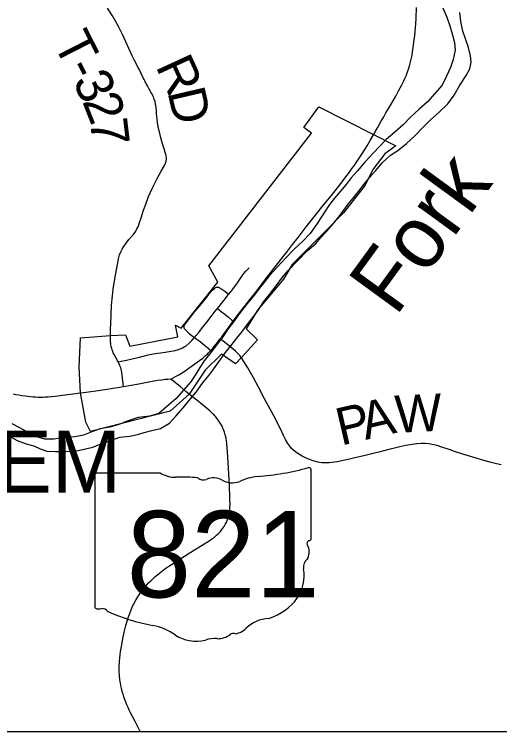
# Model space of a CAD drawing. Extents: x -10.5 to 40.6, y -3.2 to 22.
# Drawn here: x -8.513 to -7.773, y 14.1 to 15.194 of the extents above; entities that cross this region are included whole.
import ezdxf

# ---------------------------------------------------------------- set-up
doc = ezdxf.new("R2010")
doc.units = 0
for name, color, linetype in [('GM_X_City_Street', 7, 'Continuous'), ('GM_X_Corporation_Text', 7, 'Continuous'), ('GM_X_Major_River', 7, 'Continuous'), ('GM_X_Major_River_Text', 7, 'Continuous'), ('GM_X_State_Location', 7, 'Continuous'), ('GM_X_State_Route', 7, 'Continuous'), ('GM_X_State_Shield', 7, 'Continuous'), ('GM_X_Township_Road', 7, 'Continuous'), ('GM_X_Township_Road_Text', 7, 'Continuous'), ('GM_X_Township_Text', 7, 'Continuous'), ('SH_Text', 7, 'Continuous')]:
    doc.layers.add(name, color=color, linetype=linetype)

msp = doc.modelspace()

# ---------------------------------------------------------------- linework, layer by layer
at = {"layer": 'GM_X_City_Street'}
for points in [[(-8.3549, 14.6638), (-8.35, 14.6648), (-8.3422, 14.6664), (-8.3332, 14.6684), (-8.3223, 14.6711), (-8.309, 14.6743), (-8.3011, 14.6759), (-8.2943, 14.6769), (-8.2863, 14.6781), (-8.268, 14.6813), (-8.2626, 14.6828), (-8.2568, 14.685), (-8.254, 14.6864), (-8.2509, 14.6884), (-8.2466, 14.6921), (-8.2422, 14.6964), (-8.2389, 14.7002), (-8.2385, 14.7008), (-8.2359, 14.7041), (-8.2317, 14.7087), (-8.229, 14.7121), (-8.2259, 14.716), (-8.2193, 14.7243), (-8.213, 14.7327), (-8.2066, 14.7411), (-8.2033, 14.7451), (-8.2008, 14.7482), (-8.1935, 14.7574), (-8.1913, 14.7602), (-8.1901, 14.7619), (-8.1889, 14.7636), (-8.1864, 14.7666), (-8.183, 14.7706), (-8.1799, 14.7744), (-8.173, 14.784), (-8.1669, 14.7934), (-8.1633, 14.7984), (-8.1601, 14.8022), (-8.1557, 14.8067), (-8.1549, 14.8076)], [(-8.2546, 14.7169), (-8.2543, 14.7181), (-8.254, 14.7186), (-8.2534, 14.7197), (-8.2523, 14.7212), (-8.2442, 14.732), (-8.2377, 14.7403), (-8.2302, 14.7494), (-8.2177, 14.765), (-8.2163, 14.7667), (-8.2145, 14.7688), (-8.2132, 14.7703), (-8.2118, 14.7718), (-8.2103, 14.7733), (-8.2087, 14.7748), (-8.2079, 14.7755), (-8.2073, 14.776), (-8.2067, 14.7764), (-8.2057, 14.777), (-8.205, 14.7774), (-8.204, 14.7777), (-8.2029, 14.7778), (-8.2017, 14.7775), (-8.2009, 14.7771), (-8.2002, 14.7768), (-8.1994, 14.7763), (-8.1986, 14.7758), (-8.1975, 14.7751), (-8.1967, 14.7746), (-8.192, 14.7714), (-8.1901, 14.7699), (-8.187, 14.7672), (-8.1864, 14.7666)], [(-8.2033, 14.7451), (-8.2014, 14.7436), (-8.1977, 14.7406), (-8.1923, 14.7363), (-8.1866, 14.7317), (-8.1814, 14.7275), (-8.1793, 14.7258)], [(-8.2546, 14.7169), (-8.2546, 14.7158), (-8.2541, 14.7147), (-8.2533, 14.7137), (-8.2527, 14.713), (-8.2521, 14.7124), (-8.2471, 14.7077), (-8.2415, 14.703), (-8.2385, 14.7008), (-8.2363, 14.6991), (-8.2299, 14.6946), (-8.2231, 14.6894), (-8.2179, 14.6851), (-8.2169, 14.6843), (-8.2132, 14.681)]]:
    msp.add_lwpolyline(points, dxfattribs=at)
at = {"layer": 'GM_X_Major_River'}
for points in [[(-7.8595, 15.2033), (-7.8536, 15.1894), (-7.8489, 15.1761), (-7.8453, 15.1637), (-7.8421, 15.1504), (-7.8411, 15.1387), (-7.844, 15.1246), (-7.848, 15.1124), (-7.8539, 15.0991), (-7.8609, 15.0857), (-7.8717, 15.073), (-7.8833, 15.06), (-7.8957, 15.0488), (-7.9092, 15.0368), (-7.92, 15.0253), (-7.9331, 15.0137), (-7.9459, 15.0026), (-7.9563, 14.9922), (-7.9653, 14.9826), (-7.9784, 14.968), (-7.9903, 14.9545), (-7.9997, 14.9442), (-8.0071, 14.9342), (-8.0161, 14.9234), (-8.0276, 14.91), (-8.0343, 14.9004), (-8.0436, 14.8863), (-8.0522, 14.8729), (-8.0622, 14.8595), (-8.0734, 14.8479), (-8.0869, 14.8352), (-8.0992, 14.8225), (-8.1123, 14.8083), (-8.1239, 14.7956), (-8.131, 14.786), (-8.1399, 14.7757), (-8.1466, 14.7661), (-8.1575, 14.753), (-8.1686, 14.7392), (-8.1787, 14.7247), (-8.1873, 14.7136), (-8.1951, 14.7021), (-8.204, 14.6906), (-8.2152, 14.6756), (-8.2234, 14.6653), (-8.2304, 14.6549), (-8.2364, 14.645), (-8.2442, 14.6327), (-8.2554, 14.6201), (-8.267, 14.6074), (-8.2812, 14.5954), (-8.2928, 14.585), (-8.3068, 14.581), (-8.3242, 14.5789), (-8.3393, 14.5738), (-8.3536, 14.5683), (-8.3676, 14.5643), (-8.382, 14.5614), (-8.3948, 14.5571), (-8.4076, 14.552), (-8.4209, 14.5495), (-8.4413, 14.5477), (-8.453, 14.5457), (-8.4667, 14.5459), (-8.4789, 14.5495), (-8.4918, 14.5561), (-8.5056, 14.5639), (-8.5163, 14.5691)], [(-8.5225, 14.5516), (-8.5087, 14.5438), (-8.495, 14.5386), (-8.4832, 14.5358), (-8.4737, 14.5313), (-8.4634, 14.5277), (-8.4509, 14.5271), (-8.4388, 14.5269), (-8.4259, 14.5274), (-8.4157, 14.5287), (-8.4043, 14.5311), (-8.3934, 14.5339), (-8.3798, 14.5391), (-8.3666, 14.5438), (-8.3519, 14.5489), (-8.3367, 14.5506), (-8.3254, 14.5531), (-8.3152, 14.5563), (-8.3035, 14.5591), (-8.2899, 14.5623), (-8.2763, 14.5701), (-8.2666, 14.5812), (-8.2558, 14.5935), (-8.2476, 14.6038), (-8.2356, 14.6173), (-8.226, 14.6311), (-8.2163, 14.643), (-8.2088, 14.6529), (-8.2014, 14.6637), (-8.191, 14.6782), (-8.1809, 14.6905), (-8.1738, 14.7001), (-8.1652, 14.7104), (-8.157, 14.7216), (-8.1481, 14.7334), (-8.1406, 14.743), (-8.1325, 14.7557), (-8.1239, 14.7664), (-8.1123, 14.7817), (-8.1042, 14.7929), (-8.0956, 14.8032), (-8.0668, 14.8328), (-8.0537, 14.8436), (-8.0451, 14.8536), (-8.0365, 14.8632), (-8.0268, 14.8744), (-8.016, 14.8874), (-8.004, 14.9039), (-7.9962, 14.9135), (-7.9884, 14.9234), (-7.9798, 14.9346), (-7.9716, 14.9449), (-7.9619, 14.9553), (-7.9522, 14.9672), (-7.9395, 14.9787), (-7.9282, 14.9857), (-7.9151, 14.9965), (-7.9023, 15.0085), (-7.8892, 15.0219), (-7.8784, 15.0327), (-7.8653, 15.0446), (-7.8522, 15.057), (-7.8425, 15.0704), (-7.834, 15.0853), (-7.8243, 15.1002), (-7.8188, 15.1105), (-7.8166, 15.1208), (-7.8175, 15.1303), (-7.8204, 15.1431), (-7.8259, 15.1575), (-7.829, 15.1681), (-7.8323, 15.1828), (-7.834, 15.1965)]]:
    msp.add_lwpolyline(points, dxfattribs=at)
at = {"layer": 'GM_X_State_Route'}
for points in [[(-7.9653, 15.0099), (-7.9636, 15.0131), (-7.9618, 15.0164), (-7.9594, 15.0207), (-7.9563, 15.026), (-7.9536, 15.0309), (-7.9498, 15.0373), (-7.9464, 15.0433), (-7.9417, 15.0513), (-7.9321, 15.068), (-7.9273, 15.0767), (-7.9229, 15.0849), (-7.9194, 15.0921), (-7.9172, 15.0965), (-7.9157, 15.0999), (-7.9135, 15.1057), (-7.912, 15.1101), (-7.9105, 15.1151), (-7.9094, 15.1192), (-7.9084, 15.1234), (-7.9075, 15.1271), (-7.9067, 15.1312), (-7.9058, 15.1361), (-7.9042, 15.1465), (-7.9033, 15.1551), (-7.9026, 15.1606), (-7.902, 15.1674), (-7.9015, 15.1729), (-7.9011, 15.1791), (-7.9005, 15.1878), (-7.8998, 15.2038)], [(-8.2742, 14.6374), (-8.2672, 14.6412), (-8.261, 14.6447), (-8.2539, 14.6491), (-8.2486, 14.6529), (-8.2305, 14.6659), (-8.2256, 14.6696), (-8.2213, 14.6732), (-8.2187, 14.6755), (-8.2168, 14.6773), (-8.2132, 14.681), (-8.2111, 14.6835), (-8.2087, 14.6864), (-8.2052, 14.6907), (-8.2022, 14.6947), (-8.1997, 14.6982), (-8.1991, 14.6989), (-8.1974, 14.7011), (-8.1931, 14.7072), (-8.1887, 14.7132), (-8.1852, 14.7181), (-8.182, 14.7222), (-8.1793, 14.7258), (-8.1711, 14.7365), (-8.164, 14.7458), (-8.1585, 14.7528), (-8.1532, 14.7594), (-8.1465, 14.7682), (-8.1404, 14.7762), (-8.126, 14.7949), (-8.1028, 14.8247), (-8.0982, 14.8305), (-8.0903, 14.8408), (-8.0887, 14.8427), (-8.0803, 14.8535), (-8.0679, 14.8697), (-8.0558, 14.8847), (-8.0477, 14.8949), (-8.045, 14.8983), (-8.032, 14.9145), (-8.0238, 14.9245), (-8.0147, 14.9363), (-8.0077, 14.9457), (-8.0022, 14.953), (-7.9977, 14.9592), (-7.9941, 14.9642), (-7.9913, 14.9682), (-7.9851, 14.9774), (-7.9821, 14.9821), (-7.9753, 14.9933), (-7.9704, 15.0013), (-7.9653, 15.0099)], [(-8.2742, 14.6374), (-8.279, 14.637), (-8.2832, 14.6366), (-8.288, 14.636), (-8.2945, 14.6352), (-8.3079, 14.6328), (-8.3234, 14.6299), (-8.3466, 14.6256), (-8.3557, 14.624), (-8.3815, 14.6203), (-8.4036, 14.6172), (-8.4119, 14.616)], [(-8.2467, 14.6146), (-8.2509, 14.6181), (-8.2599, 14.6256), (-8.2703, 14.6342), (-8.2742, 14.6374)], [(-8.4737, 14.6096), (-8.4764, 14.6096), (-8.4807, 14.6099), (-8.4845, 14.6101), (-8.4881, 14.6104), (-8.4922, 14.6108), (-8.496, 14.6113), (-8.5015, 14.6121), (-8.506, 14.6128), (-8.5105, 14.6137), (-8.5142, 14.6146)], [(-8.4119, 14.616), (-8.4508, 14.6109), (-8.4564, 14.6104), (-8.4614, 14.61), (-8.4655, 14.6097), (-8.4689, 14.6096), (-8.4729, 14.6096), (-8.4737, 14.6096)], [(-8.1847, 14.4355), (-8.1843, 14.4399), (-8.1842, 14.4431), (-8.1841, 14.446), (-8.1841, 14.4484), (-8.1842, 14.4509), (-8.1842, 14.454), (-8.1843, 14.4571), (-8.1844, 14.4607), (-8.1845, 14.4632), (-8.1848, 14.4686), (-8.1849, 14.4716), (-8.1851, 14.4752), (-8.187, 14.5104), (-8.1879, 14.5267), (-8.1889, 14.5384), (-8.189, 14.5403), (-8.1893, 14.5422), (-8.1895, 14.5437), (-8.1898, 14.5458), (-8.19, 14.547), (-8.1903, 14.5484), (-8.1906, 14.5499), (-8.191, 14.5512), (-8.1914, 14.5527), (-8.1919, 14.5545), (-8.1925, 14.5564), (-8.1934, 14.5592), (-8.1939, 14.5604), (-8.1944, 14.5615), (-8.195, 14.5629), (-8.1956, 14.5641), (-8.1968, 14.5665), (-8.198, 14.5686), (-8.1996, 14.5712), (-8.201, 14.5733), (-8.2028, 14.5757), (-8.2037, 14.577), (-8.2049, 14.5784), (-8.206, 14.5798), (-8.2073, 14.5814), (-8.2085, 14.5828), (-8.2099, 14.5842), (-8.2112, 14.5855), (-8.2126, 14.5867), (-8.2149, 14.5889), (-8.2181, 14.5916), (-8.2261, 14.5981), (-8.235, 14.6052), (-8.2409, 14.6099), (-8.246, 14.614), (-8.2467, 14.6146)], [(-8.321, 14.1), (-8.3289, 14.1155), (-8.3357, 14.1288), (-8.3377, 14.1327), (-8.3395, 14.1367), (-8.3414, 14.1408), (-8.3429, 14.1447), (-8.3445, 14.149), (-8.3459, 14.153), (-8.3472, 14.1569), (-8.3485, 14.1612), (-8.3497, 14.1661), (-8.3506, 14.1704), (-8.3513, 14.1743), (-8.3517, 14.1766), (-8.352, 14.1788), (-8.3523, 14.1811), (-8.3526, 14.1837), (-8.3528, 14.187), (-8.353, 14.1903), (-8.3531, 14.1943), (-8.353, 14.1986), (-8.3526, 14.2071), (-8.3522, 14.2122), (-8.3517, 14.217), (-8.351, 14.2223), (-8.3502, 14.2274), (-8.3487, 14.2352), (-8.3474, 14.242), (-8.3453, 14.2517), (-8.3439, 14.2578), (-8.3428, 14.262), (-8.341, 14.2683), (-8.3394, 14.2733), (-8.3379, 14.2776), (-8.3365, 14.2816), (-8.3349, 14.2855), (-8.3332, 14.2896), (-8.3321, 14.2921), (-8.331, 14.2941), (-8.3291, 14.2978), (-8.3272, 14.3013), (-8.3248, 14.3054), (-8.3227, 14.3088), (-8.321, 14.3113), (-8.3191, 14.3139), (-8.3168, 14.3172), (-8.3142, 14.3203), (-8.3125, 14.3222), (-8.3108, 14.324), (-8.3083, 14.3268), (-8.305, 14.33), (-8.302, 14.3329), (-8.2989, 14.3358), (-8.296, 14.3383), (-8.2922, 14.3413), (-8.2887, 14.3441), (-8.2862, 14.346), (-8.2835, 14.348), (-8.276, 14.3531), (-8.2708, 14.3565), (-8.2536, 14.3677), (-8.2384, 14.3772), (-8.2243, 14.3857), (-8.2219, 14.3872), (-8.2198, 14.3885), (-8.2177, 14.3898), (-8.2158, 14.3911), (-8.2134, 14.3927), (-8.211, 14.3943), (-8.2091, 14.3957), (-8.2078, 14.3966), (-8.2067, 14.3975), (-8.2046, 14.3993), (-8.2023, 14.4014), (-8.2005, 14.4032), (-8.1987, 14.4053), (-8.1964, 14.4083), (-8.1949, 14.4104), (-8.1932, 14.413), (-8.1915, 14.4156), (-8.1901, 14.4181), (-8.1891, 14.42), (-8.1883, 14.4219), (-8.1873, 14.4244), (-8.1867, 14.4267), (-8.1861, 14.4285), (-8.1857, 14.4302), (-8.1852, 14.4325), (-8.1847, 14.4355)]]:
    msp.add_lwpolyline(points, dxfattribs=at)
at = {"layer": 'GM_X_State_Shield'}
for p, q in [((-8.3901, 14.4908), (-8.3901, 14.2906)), ((-8.2904, 14.4942), (-8.3869, 14.4942)), ((-8.0606, 14.3945), (-8.0606, 14.4992)), ((-8.0606, 14.3945), (-8.0606, 14.3945))]:
    msp.add_line(p, q, dxfattribs=at)
for centre, major_axis, start_param, end_param in [((-8.178, 14.767), (0.3495, 0), 4.814394, 5.042369), ((-8.0642, 14.4996), (0.00367, 0), 6.141152, 7.989035), ((-8.3864, 14.4912), (0.00382, 0), 1.712693, 3.28349), ((-8.2674, 14.5174), (0.037, 0), 4.042523, 4.731795), ((-8.2551, 14.3818), (0.133, 0), 1.404758, 1.657858), ((-8.2249, 14.4922), (0.0107, 0), 3.836095, 5.185415), ((-8.2092, 14.4691), (0.0222, 0), 0.950623, 2.079405), ((-8.1806, 14.5008), (0.0267, 0), 4.081561, 5.145723), ((-8.1334, 14.4331), (0.0703, 0), 1.699011, 2.107814), ((-8.0614, 14.3868), (0.00568, 0), 1.883978, 3.671073), ((-8.0645, 14.3941), (0.00393, 0), 5.05454, 6.418171), ((-8.0975, 14.3736), (0.0341, 0), 5.934695, 6.695948), ((-8.0474, 14.3507), (0.0248, 0), 2.387724, 3.262537), ((-8.1584, 14.3373), (0.0874, 0), 5.101752, 6.440018), ((-8.3863, 14.2902), (0.00385, 0), 3.00124, 4.508301), ((-8.3857, 14.3107), (0.0294, 0), 4.665946, 4.897461), ((-8.3797, 14.2791), (0.0106, 0), 0.519207, 1.627899), ((-8.2459, 14.4589), (0.2524, 0), 4.195997, 4.488961), ((-8.1215, 14.2344), (0.0479, 0), 1.647645, 2.488434), ((-8.3212, 14.2007), (0.079, 0), 0.823519, 1.323587), ((-8.179, 14.2437), (0.00752, 0), 1.147584, 2.315152), ((-8.1822, 14.2712), (0.0282, 0), 4.937069, 5.64225), ((-8.2357, 14.2781), (0.0501, 0), 4.026481, 4.996735), ((-8.2068, 14.2089), (0.0412, 0), 1.495662, 1.94098), ((-8.2031, 14.2631), (0.0267, 0), 4.691044, 5.507374)]:
    msp.add_ellipse(centre, major_axis=major_axis, ratio=0.8, start_param=start_param, end_param=end_param, dxfattribs=at)
at = {"layer": 'GM_X_Township_Road'}
for points in [[(-8.3662, 14.714), (-8.366, 14.7213), (-8.3646, 14.7504), (-8.3634, 14.7646), (-8.3623, 14.7744), (-8.3598, 14.7904), (-8.3559, 14.8124), (-8.3541, 14.8209), (-8.3525, 14.8269), (-8.3507, 14.8316), (-8.3488, 14.8355), (-8.3463, 14.8397), (-8.3426, 14.8448), (-8.3383, 14.8501), (-8.3318, 14.8576), (-8.3285, 14.862), (-8.326, 14.8663), (-8.3239, 14.8707), (-8.322, 14.876), (-8.3198, 14.8831), (-8.316, 14.8949), (-8.3127, 14.9043), (-8.3082, 14.9159), (-8.3029, 14.9278), (-8.2995, 14.9351), (-8.2941, 14.9455), (-8.2893, 14.9542), (-8.2839, 14.9633), (-8.2823, 14.9667), (-8.2814, 14.9696), (-8.2811, 14.9721), (-8.281, 14.9745), (-8.2816, 14.9782), (-8.2829, 14.983), (-8.2845, 14.9883), (-8.2865, 14.9948), (-8.2885, 15.0019), (-8.29, 15.0072), (-8.2907, 15.0096), (-8.2919, 15.0143), (-8.2923, 15.016), (-8.2928, 15.0183), (-8.2931, 15.0195), (-8.2935, 15.0212), (-8.2939, 15.0236), (-8.2942, 15.0253), (-8.2945, 15.0276), (-8.2948, 15.0299), (-8.295, 15.0316), (-8.2952, 15.0327), (-8.2954, 15.0349), (-8.2957, 15.0366), (-8.2957, 15.0376), (-8.2958, 15.0387), (-8.296, 15.0415), (-8.2963, 15.0443), (-8.2965, 15.046), (-8.2965, 15.0476), (-8.2968, 15.051), (-8.2972, 15.0545), (-8.2976, 15.0562), (-8.2978, 15.0573), (-8.2985, 15.0607), (-8.2996, 15.0641), (-8.3005, 15.0662), (-8.3014, 15.0684), (-8.3035, 15.0726), (-8.305, 15.0751), (-8.3061, 15.0771), (-8.3081, 15.0807), (-8.3095, 15.0833), (-8.31, 15.0843), (-8.3114, 15.087), (-8.3133, 15.0906), (-8.314, 15.0922), (-8.3151, 15.0942), (-8.3159, 15.0958), (-8.3202, 15.1045), (-8.3224, 15.1088), (-8.3229, 15.1099), (-8.3245, 15.1132), (-8.3279, 15.1198), (-8.3301, 15.1242), (-8.3331, 15.1303), (-8.3483, 15.163), (-8.3538, 15.1741), (-8.3591, 15.184), (-8.3635, 15.1914), (-8.3709, 15.2029)], [(-8.3664, 14.7042), (-8.3664, 14.7089), (-8.3662, 14.714)], [(-8.3549, 14.6638), (-8.3609, 14.6752), (-8.3621, 14.6777), (-8.3629, 14.6797), (-8.3638, 14.6822), (-8.3645, 14.6843), (-8.3652, 14.6873), (-8.3657, 14.6894), (-8.366, 14.6916), (-8.3662, 14.6941), (-8.3663, 14.6965), (-8.3664, 14.6987), (-8.3664, 14.7008), (-8.3663, 14.7033), (-8.3664, 14.7042)], [(-8.1671, 14.6704), (-8.1693, 14.6732), (-8.1726, 14.6769), (-8.1758, 14.6798), (-8.1824, 14.6854), (-8.1945, 14.6952), (-8.1991, 14.6989)], [(-7.7707, 14.5069), (-7.7781, 14.5083), (-7.7859, 14.5102), (-7.7973, 14.5134), (-7.8139, 14.5184), (-7.8293, 14.5232), (-7.8417, 14.5273), (-7.8488, 14.5296), (-7.8612, 14.5339), (-7.8683, 14.536), (-7.8733, 14.5371), (-7.8811, 14.5386), (-7.8866, 14.5391), (-7.8928, 14.5392), (-7.8996, 14.5388), (-7.9064, 14.5379), (-7.9168, 14.536), (-7.9253, 14.5341), (-7.9313, 14.5326), (-7.9422, 14.5299), (-7.9572, 14.5262), (-7.9657, 14.5241), (-7.9783, 14.521), (-7.9977, 14.5163), (-8.0019, 14.5154), (-8.0092, 14.5137), (-8.0207, 14.5113), (-8.0287, 14.5101), (-8.033, 14.5097), (-8.038, 14.5096), (-8.0442, 14.51), (-8.0503, 14.511), (-8.0575, 14.513), (-8.0628, 14.5147), (-8.0691, 14.5174), (-8.0742, 14.5198), (-8.0784, 14.5224), (-8.0824, 14.5248), (-8.0865, 14.528), (-8.0903, 14.5315), (-8.093, 14.5351), (-8.0959, 14.5393), (-8.0994, 14.5455), (-8.1026, 14.5516), (-8.1069, 14.5604), (-8.1091, 14.5652), (-8.1145, 14.5757), (-8.1319, 14.6086), (-8.1407, 14.6251), (-8.1491, 14.6403), (-8.157, 14.6544), (-8.1666, 14.6697), (-8.1671, 14.6704)], [(-8.3466, 14.6256), (-8.3472, 14.6303), (-8.3482, 14.6391), (-8.3488, 14.6444), (-8.349, 14.6464), (-8.3493, 14.6482), (-8.3497, 14.6503), (-8.3502, 14.6525), (-8.3508, 14.6545), (-8.3515, 14.6566), (-8.3524, 14.6587), (-8.3535, 14.661), (-8.3549, 14.6638)]]:
    msp.add_lwpolyline(points, dxfattribs=at)
at = {"layer": 'GM_X_Township_Text'}
msp.add_lwpolyline([(-8.2675, 14.7197), (-8.2588, 14.7152), (-8.2026, 14.7851), (-8.2165, 14.81), (-8.06, 15.0122), (-8.0718, 15.0209), (-8.0488, 15.0524), (-7.9655, 15.0104), (-7.9313, 14.993), (-7.9483, 14.9808), (-7.9665, 14.9572), (-7.9782, 14.9331), (-8.0112, 14.8909), (-8.0358, 14.866), (-8.0895, 14.8123), (-8.1024, 14.79), (-8.1423, 14.7427), (-8.1597, 14.7143), (-8.1423, 14.6972), (-8.1668, 14.6703), (-8.1757, 14.6607), (-8.1973, 14.6756), (-8.222, 14.6512), (-8.2462, 14.6145), (-8.2756, 14.5885), (-8.3967, 14.5574), (-8.4042, 14.5717), (-8.4121, 14.6166), (-8.4143, 14.656), (-8.4121, 14.7006), (-8.3665, 14.7038), (-8.3436, 14.7051), (-8.3371, 14.6879), (-8.2638, 14.7017)], close=True, dxfattribs=at)
at = {"layer": 'SH_Text'}
msp.add_lwpolyline([(-10.5445, 16.0741), (-10.5445, 14.1), (-6.2122, 14.1)], dxfattribs=at)

# ---------------------------------------------------------------- texts
at = {"layer": 'GM_X_Corporation_Text'}
msp.add_text('LOWER SALEM', height=0.094697, rotation=0, dxfattribs=at).set_placement((-9.2789, 14.4643))
at = {"layer": 'GM_X_Major_River_Text'}
msp.add_text('Fork', height=0.09473, rotation=53.9104, dxfattribs=at).set_placement((-7.9316, 14.7314))
at = {"layer": 'GM_X_State_Location'}
for s, p in [('s', (-8.229, 14.3774)), ('r', (-8.2291, 14.3774))]:
    msp.add_text(s, height=0.000189, dxfattribs=at).set_placement(p)
msp.add_text('821', height=0.000189, rotation=0, dxfattribs=at).set_placement((-8.2959, 14.3636))
at = {"layer": 'GM_X_State_Shield'}
msp.add_text('821', height=0.13184, dxfattribs=at).set_placement((-8.3416, 14.3047))
at = {"layer": 'GM_X_Township_Road_Text'}
for s, rotation, p in [('T', 297.0845, (-8.4545, 15.15)), ('R', 294.7111, (-8.2982, 15.1146)), ('-', 296.8583, (-8.4352, 15.1122)), ('3', 295.9041, (-8.4248, 15.0916)), ('D', 283.1898, (-8.2797, 15.0751)), ('2', 291.4874, (-8.4099, 15.0612)), ('7', 276.9643, (-8.398, 15.0323)), ('W', 2.7289, (-7.9317, 14.5555)), ('P', 13.0658, (-8.0151, 14.5359)), ('A', 12.9733, (-7.9778, 14.5446))]:
    msp.add_text(s, height=0.0568, rotation=rotation, dxfattribs=at).set_placement(p)

doc.saveas('drawing.dxf')
